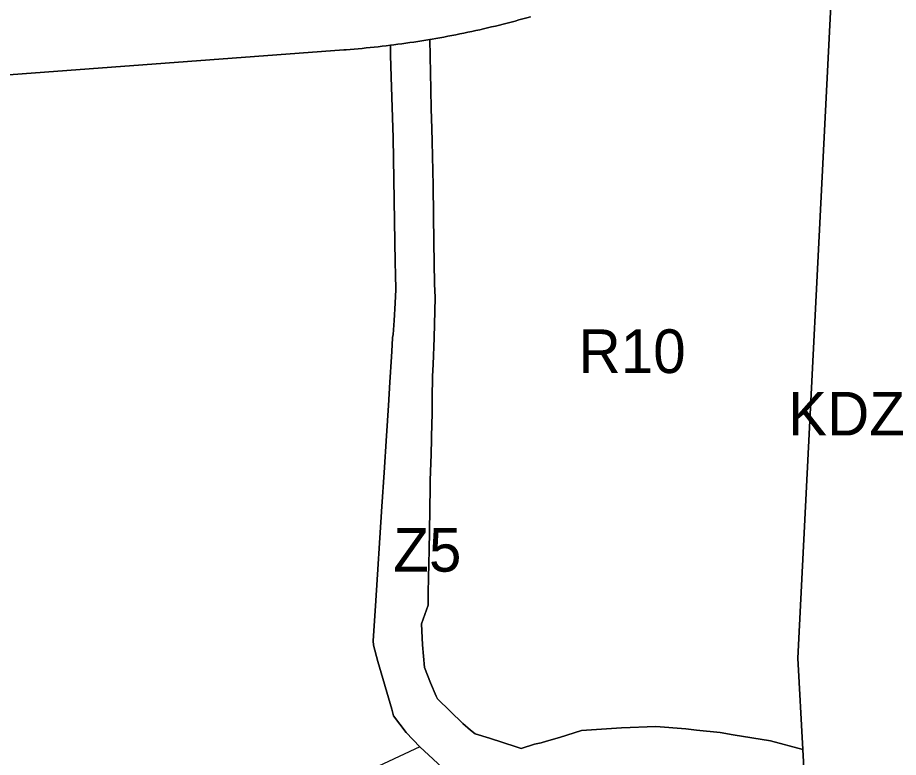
# Model space of a CAD drawing. Extents: x 7439486 to 7443435, y 5551288 to 5554556.
# Drawn here: x 7440595.5 to 7440797.2, y 5551897.3 to 5552066.8 of the extents above; entities that cross this region are included whole.
import ezdxf

# ---------------------------------------------------------------- set-up
doc = ezdxf.new("R2010")
doc.units = 0
doc.layers.add('linie_rozgraniczajace', color=7, linetype='Continuous')
doc.layers.add('oznaczenia_przeznaczen', color=7, linetype='Continuous')

msp = doc.modelspace()

# ---------------------------------------------------------------- linework, layer by layer
at = {"layer": 'linie_rozgraniczajace'}
for points in [[(7440781.88, 5552072.73), (7440774.18, 5551920.04), (7440775.35, 5551899.06), (7440767.92, 5551901.09), (7440759.38, 5551902.49), (7440756.43, 5551902.97), (7440751.01, 5551903.5), (7440748.51, 5551903.81), (7440741.64, 5551904.37), (7440733.79, 5551904.09), (7440724.61, 5551903.41), (7440719.57, 5551901.86), (7440716.59, 5551900.97), (7440715.39, 5551900.62), (7440713.89, 5551900.29), (7440710.86, 5551899.35), (7440709.66, 5551899.7), (7440703.56, 5551901.68), (7440700.28, 5551902.66), (7440699.24, 5551903.5), (7440697.46, 5551905.07), (7440691.65, 5551910.74), (7440691.38, 5551911.28), (7440690.09, 5551914.38), (7440688.71, 5551917.92), (7440688.22, 5551923.1), (7440687.98, 5551927.86)], [(7440687.98, 5551927.86), (7440689.5, 5551932.18), (7440689.49, 5551935.05), (7440689.57, 5551938.46), (7440689.72, 5551944.84), (7440689.85, 5551949.06), (7440689.99, 5551959.18), (7440690.01, 5551960.77), (7440690.22, 5551966.69), (7440690.37, 5551973.91), (7440690.44, 5551975.71), (7440690.43, 5551977.08), (7440690.46, 5551979.55), (7440690.53, 5551984.62), (7440690.67, 5551987.29), (7440690.91, 5551993.45), (7440691.09, 5552002.68), (7440691, 5552005.79), (7440690.79, 5552015.34), (7440690.71, 5552021.54), (7440690.63, 5552028.35), (7440690.42, 5552038.39), (7440690.36, 5552041.38), (7440690.19, 5552045.86), (7440690.15, 5552050.34), (7440689.9, 5552061.77), (7440690.4, 5552061.86), (7440691.31, 5552062.02), (7440692.23, 5552062.18), (7440693.14, 5552062.34), (7440694.05, 5552062.51), (7440694.96, 5552062.69), (7440695.87, 5552062.86), (7440696.78, 5552063.05), (7440697.69, 5552063.23), (7440698.6, 5552063.42), (7440699.5, 5552063.61), (7440700.41, 5552063.81), (7440701.32, 5552064.01), (7440702.22, 5552064.22), (7440703.12, 5552064.43), (7440704.03, 5552064.64), (7440704.93, 5552064.86), (7440705.83, 5552065.08), (7440706.73, 5552065.3), (7440707.63, 5552065.53), (7440708.52, 5552065.76), (7440709.42, 5552066), (7440710.32, 5552066.24), (7440711.21, 5552066.48), (7440712.11, 5552066.73), (7440713, 5552066.98)], [(7440713, 5552066.98), (7440712.11, 5552066.73), (7440711.21, 5552066.48), (7440710.32, 5552066.24), (7440709.42, 5552066), (7440708.52, 5552065.76), (7440707.63, 5552065.53), (7440706.73, 5552065.3), (7440705.83, 5552065.08), (7440704.93, 5552064.86), (7440704.03, 5552064.64), (7440703.12, 5552064.43), (7440702.22, 5552064.22), (7440701.32, 5552064.01), (7440700.41, 5552063.81), (7440699.5, 5552063.61), (7440698.6, 5552063.42)], [(7440698.6, 5552063.42), (7440697.69, 5552063.23), (7440696.78, 5552063.05), (7440695.87, 5552062.86), (7440694.96, 5552062.69), (7440694.05, 5552062.51), (7440693.14, 5552062.34), (7440692.23, 5552062.18), (7440691.31, 5552062.02), (7440690.4, 5552061.86), (7440689.9, 5552061.77), (7440688.99, 5552061.62), (7440688.07, 5552061.47), (7440687.16, 5552061.33), (7440686.24, 5552061.19), (7440685.32, 5552061.05), (7440684.4, 5552060.92), (7440683.49, 5552060.79), (7440682.57, 5552060.67), (7440681.65, 5552060.55), (7440680.86, 5552060.45), (7440679.93, 5552060.34), (7440679.01, 5552060.23), (7440678.09, 5552060.12), (7440677.17, 5552060.02), (7440676.25, 5552059.92), (7440675.33, 5552059.83), (7440674.4, 5552059.74), (7440673.48, 5552059.66), (7440672.56, 5552059.57), (7440671.63, 5552059.5), (7440670.71, 5552059.42), (7440670.22, 5552059.39), (7440570.85, 5552051.98)], [(7440570.85, 5552051.98), (7440670.22, 5552059.39), (7440670.71, 5552059.42), (7440671.63, 5552059.5), (7440672.56, 5552059.57), (7440673.48, 5552059.66), (7440674.4, 5552059.74), (7440675.33, 5552059.83), (7440676.25, 5552059.92), (7440677.17, 5552060.02), (7440678.09, 5552060.12), (7440679.01, 5552060.23), (7440679.93, 5552060.34), (7440680.86, 5552060.45), (7440680.92, 5552058.18), (7440681.07, 5552053.18), (7440681.49, 5552039.25), (7440681.99, 5552010.68), (7440682.04, 5552007.92), (7440682.14, 5552004.46), (7440681.93, 5552001.35), (7440681.73, 5551997.38), (7440681.48, 5551994.18), (7440681.38, 5551993.49), (7440681.29, 5551991.76), (7440681.1, 5551989.05), (7440680.75, 5551983.29), (7440680.43, 5551977.88), (7440679.97, 5551970.97), (7440679.41, 5551962.56), (7440678.89, 5551954.77), (7440677.46, 5551932.02), (7440676.91, 5551924.03), (7440677, 5551922.99), (7440678.01, 5551919.29), (7440681.18, 5551908.37), (7440681.58, 5551906.81), (7440684.5, 5551902.97), (7440687.6, 5551899.74), (7440576.88, 5551847.95)], [(7440693.75, 5551894.06), (7440687.6, 5551899.74), (7440684.5, 5551902.97), (7440681.58, 5551906.81), (7440681.18, 5551908.37), (7440678.01, 5551919.29), (7440677, 5551922.99), (7440676.91, 5551924.03), (7440677.46, 5551932.02), (7440678.89, 5551954.77), (7440679.41, 5551962.56), (7440679.97, 5551970.97), (7440680.43, 5551977.88), (7440680.75, 5551983.29), (7440681.1, 5551989.05), (7440681.29, 5551991.76), (7440681.38, 5551993.49), (7440681.48, 5551994.18), (7440681.73, 5551997.38), (7440681.93, 5552001.35), (7440682.14, 5552004.46), (7440682.04, 5552007.92), (7440681.99, 5552010.68), (7440681.49, 5552039.25), (7440681.07, 5552053.18), (7440680.92, 5552058.18), (7440680.86, 5552060.45), (7440681.65, 5552060.55), (7440682.57, 5552060.67), (7440683.49, 5552060.79), (7440684.4, 5552060.92), (7440685.32, 5552061.05), (7440686.24, 5552061.19), (7440687.16, 5552061.33), (7440688.07, 5552061.47), (7440688.99, 5552061.62), (7440689.9, 5552061.77), (7440690.15, 5552050.34), (7440690.19, 5552045.86), (7440690.36, 5552041.38), (7440690.42, 5552038.39), (7440690.63, 5552028.35), (7440690.71, 5552021.54), (7440690.79, 5552015.34), (7440691, 5552005.79), (7440691.09, 5552002.68), (7440690.91, 5551993.45), (7440690.67, 5551987.29), (7440690.53, 5551984.62), (7440690.46, 5551979.55), (7440690.43, 5551977.08), (7440690.44, 5551975.71), (7440690.37, 5551973.91), (7440690.22, 5551966.69), (7440690.01, 5551960.77), (7440689.99, 5551959.18), (7440689.85, 5551949.06), (7440689.72, 5551944.84), (7440689.57, 5551938.46), (7440689.49, 5551935.05), (7440689.5, 5551932.18), (7440687.98, 5551927.86), (7440688.22, 5551923.1), (7440688.71, 5551917.92), (7440690.09, 5551914.38), (7440691.38, 5551911.28), (7440691.65, 5551910.74), (7440697.46, 5551905.07), (7440699.24, 5551903.5), (7440700.28, 5551902.66), (7440703.56, 5551901.68), (7440709.66, 5551899.7), (7440710.86, 5551899.35), (7440713.89, 5551900.29), (7440715.39, 5551900.62), (7440716.59, 5551900.97), (7440719.57, 5551901.86), (7440724.61, 5551903.41), (7440733.79, 5551904.09), (7440741.64, 5551904.37), (7440748.51, 5551903.81), (7440751.01, 5551903.5), (7440756.43, 5551902.97), (7440759.38, 5551902.49), (7440767.92, 5551901.09), (7440775.35, 5551899.06), (7440776.29, 5551882.14)]]:
    msp.add_lwpolyline(points, dxfattribs=at)
msp.add_lwpolyline([(7440774.18, 5551920.04), (7440781.88, 5552072.73), (7440806.89, 5552072.31), (7440803.64, 5552007.76), (7440799.21, 5551920.11), (7440800.76, 5551892.23), (7440801.61, 5551877.02), (7440776.82, 5551882.03), (7440776.29, 5551882.14), (7440775.35, 5551899.06)], close=True, dxfattribs=at)

# ---------------------------------------------------------------- texts
at = {"layer": 'oznaczenia_przeznaczen'}
for s, p in [('R10', (7440723.98, 5551985.35)), ('KDZ3', (7440771.99, 5551971.04)), ('Z5', (7440681.53, 5551939.84))]:
    msp.add_text(s, height=10, dxfattribs=at).set_placement(p)

doc.saveas('drawing.dxf')
